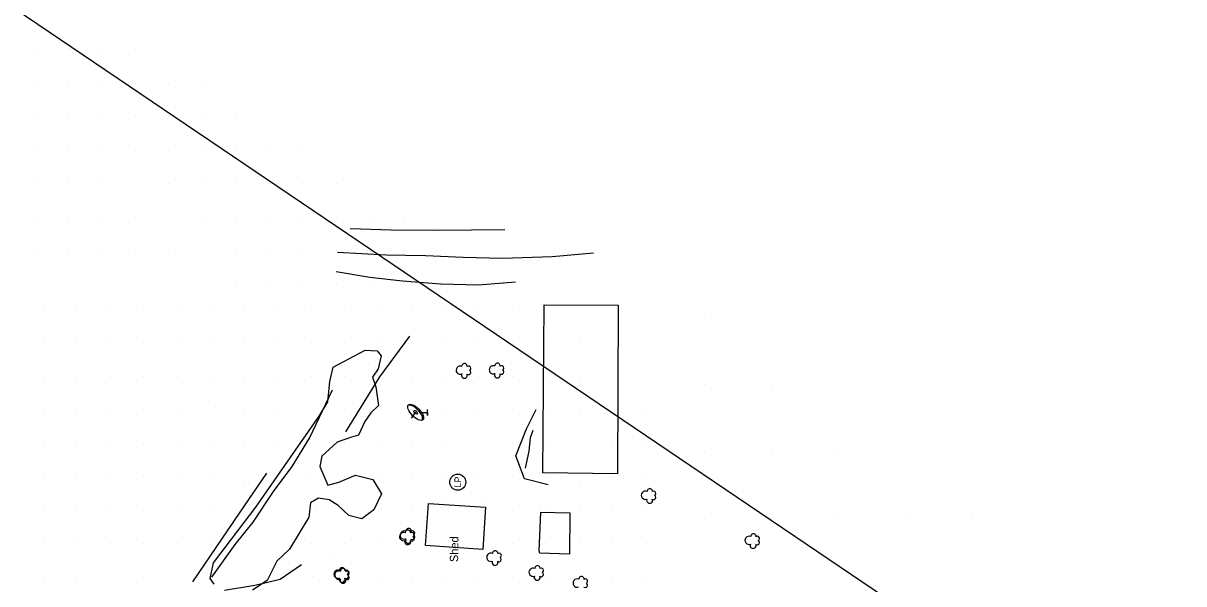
# Model space of a CAD drawing. Extents: x 19528164 to 19545171, y 7585743 to 7602745.
# Drawn here: x 19534893 to 19535586, y 7588311 to 7588646 of the extents above; entities that cross this region are included whole.
import ezdxf

# ---------------------------------------------------------------- set-up
doc = ezdxf.new("R2010")
doc.units = 0
for name, color, linetype in [('PhoBreakLine', 7, 'Continuous'), ('PhoBuilding', 7, 'Continuous'), ('PhoFence', 7, 'Continuous'), ('PhoISAEPoints', 7, 'Continuous'), ('PhoNotesDesign', 7, 'Continuous'), ('PhoSurveyLimits', 7, 'Continuous'), ('PhoVegetation', 7, 'Continuous'), ('SurBreakLine', 7, 'Continuous'), ('SurEdgeEntranceUnpaved', 7, 'Continuous'), ('SurNaturalCells', 7, 'Continuous')]:
    doc.layers.add(name, color=color, linetype=linetype)

# ---------------------------------------------------------------- blocks, each defined once
blk = doc.blocks.new('TRDC')
at = {"layer": 'PhoVegetation'}
for centre, radius, start, end in [((-6, -1.1), 3.52, 65.4824, 294.5175), ((0.1, 4), 4.92, 338.2051, 201.7949), ((4.9, -1.1), 3.21, 265.9982, 94.0018), ((-2.4, -5.9), 2.68, 142.7501, 335.3223), ((2.5, -5.8), 2.67, 206.5242, 35.4033)]:
    blk.add_arc(centre, radius, start, end, dxfattribs=at)

msp = doc.modelspace()

# ---------------------------------------------------------------- linework, layer by layer
at = {"layer": 'PhoBreakLine'}
for points in [[(19535180.52, 7588522.42), (19535140.77, 7588522.02), (19535112.64, 7588522.08), (19535088.25, 7588522.91)], [(19535080.57, 7588509.01), (19535109.62, 7588507.49), (19535133.15, 7588507.03), (19535155.59, 7588505.99), (19535179.13, 7588505.48), (19535208.86, 7588506.51), (19535233.44, 7588508.66)], [(19535186.86, 7588491.18), (19535164.83, 7588489.36), (19535142.23, 7588489.8), (19535119.54, 7588491.76), (19535100, 7588493.78), (19535079.79, 7588497.34)], [(19535085.63, 7588401.6), (19535105.96, 7588434.54), (19535123.82, 7588458.81)], [(19535005.58, 7588314.88), (19535019.47, 7588334.48), (19535030.39, 7588347.72), (19535042.37, 7588366.07), (19535053.67, 7588381.07), (19535064.02, 7588397.86), (19535077.73, 7588426.83)], [(19535206.33, 7588370.01), (19535192.35, 7588373.72), (19535187.07, 7588387.28), (19535193.48, 7588403.4), (19535199.3, 7588415.1)], [(19535192.97, 7588379.93), (19535195.03, 7588390.25), (19535195.89, 7588398.28), (19535197.49, 7588402.63)], [(19535013.09, 7588307.18), (19535031.38, 7588310.13), (19535046.51, 7588313.77), (19535059.16, 7588322.43)]]:
    msp.add_lwpolyline(points, dxfattribs=at)
at = {"layer": 'PhoBuilding'}
for points in [[(19535203.26, 7588377.18), (19535204.04, 7588477.59), (19535248.3, 7588477.29), (19535247.76, 7588376.67), (19535203.26, 7588377.18)], [(19535134.93, 7588358.89), (19535169.1, 7588356.65), (19535167.45, 7588331.51), (19535133.28, 7588333.75)], [(19535201.04, 7588330.65), (19535202.05, 7588353.65), (19535219.41, 7588353.32), (19535219.08, 7588328.67), (19535201.44, 7588329.33)]]:
    msp.add_lwpolyline(points, close=True, dxfattribs=at)
at = {"layer": 'PhoFence'}
msp.add_lwpolyline([(19534994.27, 7588312.05), (19535022.58, 7588353.76), (19535038.46, 7588376.96)], dxfattribs=at)
at = {"layer": 'PhoISAEPoints'}
for p, q in [((19534900, 7588590), (19534900, 7588590)), ((19534900, 7588570), (19534900, 7588570)), ((19534920, 7588570), (19534920, 7588570)), ((19534900, 7588550), (19534900, 7588550)), ((19534920, 7588550), (19534920, 7588550)), ((19534940, 7588550), (19534940, 7588550)), ((19534900, 7588530), (19534900, 7588530)), ((19534920, 7588530), (19534920, 7588530)), ((19534940, 7588530), (19534940, 7588530)), ((19534960, 7588530), (19534960, 7588530)), ((19534900, 7588510), (19534900, 7588510)), ((19534920, 7588510), (19534920, 7588510)), ((19534940, 7588510), (19534940, 7588510)), ((19534960, 7588510), (19534960, 7588510)), ((19534980, 7588510), (19534980, 7588510)), ((19535020, 7588490), (19535020, 7588490)), ((19534905, 7588475), (19534905, 7588475)), ((19534925, 7588475), (19534925, 7588475)), ((19534945, 7588475), (19534945, 7588475)), ((19534965, 7588475), (19534965, 7588475)), ((19534985, 7588475), (19534985, 7588475)), ((19535005, 7588475), (19535005, 7588475)), ((19535025, 7588475), (19535025, 7588475)), ((19534905, 7588455), (19534905, 7588455)), ((19534925, 7588455), (19534925, 7588455)), ((19534945, 7588455), (19534945, 7588455)), ((19534965, 7588455), (19534965, 7588455)), ((19534985, 7588455), (19534985, 7588455)), ((19535005, 7588455), (19535005, 7588455)), ((19535025, 7588455), (19535025, 7588455)), ((19535045, 7588455), (19535045, 7588455)), ((19535065, 7588455), (19535065, 7588455)), ((19534905, 7588435), (19534905, 7588435)), ((19534925, 7588435), (19534925, 7588435)), ((19534945, 7588435), (19534945, 7588435)), ((19534965, 7588435), (19534965, 7588435)), ((19534985, 7588435), (19534985, 7588435)), ((19535005, 7588435), (19535005, 7588435)), ((19535025, 7588435), (19535025, 7588435)), ((19535045, 7588435), (19535045, 7588435)), ((19535065, 7588435), (19535065, 7588435)), ((19535085, 7588435), (19535085, 7588435)), ((19534905, 7588415), (19534905, 7588415)), ((19534925, 7588415), (19534925, 7588415)), ((19534945, 7588415), (19534945, 7588415)), ((19534965, 7588415), (19534965, 7588415)), ((19534985, 7588415), (19534985, 7588415)), ((19535007.65, 7588416.93), (19535007.65, 7588416.93)), ((19535025, 7588415), (19535025, 7588415)), ((19535045, 7588415), (19535045, 7588415)), ((19535085, 7588415), (19535085, 7588415)), ((19535105, 7588415), (19535105, 7588415)), ((19534905, 7588395), (19534905, 7588395)), ((19534925, 7588395), (19534925, 7588395)), ((19534945, 7588395), (19534945, 7588395)), ((19534965, 7588395), (19534965, 7588395)), ((19534985, 7588395), (19534985, 7588395)), ((19535005, 7588395), (19535005, 7588395)), ((19535025, 7588395), (19535025, 7588395)), ((19535045, 7588395), (19535045, 7588395)), ((19535085, 7588395), (19535085, 7588395)), ((19535105, 7588395), (19535105, 7588395)), ((19535125, 7588395), (19535125, 7588395)), ((19535145, 7588395), (19535145, 7588395)), ((19535063.88, 7588376.86), (19535063.88, 7588376.86)), ((19534905, 7588375), (19534905, 7588375)), ((19534925, 7588375), (19534925, 7588375)), ((19534945, 7588375), (19534945, 7588375)), ((19534965, 7588375), (19534965, 7588375)), ((19534985, 7588375), (19534985, 7588375)), ((19535005, 7588375), (19535005, 7588375)), ((19535085, 7588375), (19535085, 7588375)), ((19535105, 7588375), (19535105, 7588375)), ((19535125, 7588375), (19535125, 7588375)), ((19535145, 7588375), (19535145, 7588375)), ((19535165, 7588375), (19535165, 7588375)), ((19535025.11, 7588368.9), (19535025.11, 7588368.9)), ((19535145.96, 7588361.36), (19535145.96, 7588361.36)), ((19535167.49, 7588359.83), (19535167.49, 7588359.83)), ((19534905, 7588355), (19534905, 7588355)), ((19534925, 7588355), (19534925, 7588355)), ((19534945, 7588355), (19534945, 7588355)), ((19534965, 7588355), (19534965, 7588355)), ((19534985, 7588355), (19534985, 7588355)), ((19535005, 7588355), (19535005, 7588355)), ((19535067.36, 7588354.34), (19535067.36, 7588354.34)), ((19535085, 7588355), (19535085, 7588355)), ((19535105, 7588355), (19535105, 7588355)), ((19535125, 7588355), (19535125, 7588355)), ((19534905, 7588335), (19534905, 7588335)), ((19534925.42, 7588335.97), (19534925.42, 7588335.97)), ((19534945, 7588335), (19534945, 7588335)), ((19534965, 7588335), (19534965, 7588335)), ((19534985, 7588335), (19534985, 7588335)), ((19535005, 7588335), (19535005, 7588335)), ((19535056.79, 7588337.85), (19535056.79, 7588337.85)), ((19535065, 7588335), (19535065, 7588335)), ((19535085, 7588335), (19535085, 7588335)), ((19535105, 7588335), (19535105, 7588335)), ((19535125, 7588335), (19535125, 7588335)), ((19535147.45, 7588332.11), (19535147.45, 7588332.11)), ((19535168.44, 7588331.03), (19535168.44, 7588331.03)), ((19535045.88, 7588325.22), (19535045.88, 7588325.22)), ((19535078.4, 7588327.09), (19535078.4, 7588327.09)), ((19534905, 7588315), (19534905, 7588315)), ((19534925, 7588315), (19534925, 7588315)), ((19534965, 7588315), (19534965, 7588315)), ((19535065.97, 7588315.29), (19535065.97, 7588315.29)), ((19535065.97, 7588315.29), (19535065.97, 7588315.29)), ((19535085, 7588315), (19535085, 7588315)), ((19535105, 7588315), (19535105, 7588315)), ((19535125, 7588315), (19535125, 7588315)), ((19535145, 7588315), (19535145, 7588315)), ((19535165, 7588315), (19535165, 7588315))]:
    msp.add_line(p, q, dxfattribs=at)
at = {"layer": 'PhoSurveyLimits'}
msp.add_lwpolyline([(19533878.26, 7590287.69), (19534414.23, 7589271.02), (19534620.47, 7588835.55), (19535976.6, 7587917.86), (19535872.2, 7587743.02), (19536196.76, 7587523.02), (19536087.66, 7587353.22), (19535761.89, 7587557.7), (19535245.62, 7586693.59), (19535240.5, 7586278.66), (19534925.52, 7586278.66), (19534905.11, 7587015.02), (19534733.57, 7587498.57), (19533471.56, 7588328.44)], dxfattribs=at)
at = {"layer": 'PhoVegetation'}
msp.add_lwpolyline([(19535007.1, 7588310.73), (19535004.64, 7588314.07), (19535006.7, 7588323.37), (19535031.87, 7588356.72), (19535069.76, 7588411.12), (19535074.94, 7588419.69), (19535076.06, 7588431.82), (19535078.05, 7588440.24), (19535097.22, 7588450.57), (19535104.4, 7588450.14), (19535106.65, 7588447.11), (19535104.86, 7588439.31), (19535101.52, 7588434.39), (19535103.48, 7588428.66), (19535105.06, 7588417.44), (19535100.55, 7588413.1), (19535097.01, 7588407.89), (19535093.28, 7588399.64), (19535089.05, 7588398.57), (19535080.46, 7588395.54), (19535071.39, 7588387.19), (19535070.12, 7588381.04), (19535074.81, 7588369.92), (19535081.47, 7588371.59), (19535091.48, 7588375.85), (19535101.71, 7588373.29), (19535106.83, 7588364.66), (19535102.35, 7588355.11), (19535095.22, 7588349.7), (19535087.47, 7588351.7), (19535080.96, 7588357.67), (19535075.74, 7588360.99), (19535069.35, 7588362.08), (19535064.57, 7588359.28), (19535063.57, 7588350.69), (19535051.91, 7588331.57), (19535044.5, 7588324.46), (19535038.75, 7588312.82), (19535029.94, 7588307.12)], dxfattribs=at)
msp.add_lwpolyline([(19535007.1, 7588310.73), (19535004.64, 7588314.07), (19535006.7, 7588323.37), (19535031.87, 7588356.72), (19535069.76, 7588411.12), (19535074.94, 7588419.69), (19535076.06, 7588431.82), (19535078.05, 7588440.24), (19535097.22, 7588450.57), (19535104.4, 7588450.14), (19535106.65, 7588447.11), (19535104.86, 7588439.31), (19535101.52, 7588434.39), (19535103.48, 7588428.66), (19535105.06, 7588417.44), (19535100.55, 7588413.1), (19535097.01, 7588407.89), (19535093.28, 7588399.64), (19535089.05, 7588398.57), (19535080.46, 7588395.54), (19535071.39, 7588387.19), (19535070.12, 7588381.04), (19535074.81, 7588369.92), (19535081.47, 7588371.59), (19535091.48, 7588375.85), (19535101.71, 7588373.29), (19535106.83, 7588364.66), (19535102.35, 7588355.11), (19535095.22, 7588349.7), (19535087.47, 7588351.7), (19535080.96, 7588357.67), (19535075.74, 7588360.99), (19535069.35, 7588362.08), (19535064.57, 7588359.28), (19535063.57, 7588350.69), (19535051.91, 7588331.57), (19535044.5, 7588324.46), (19535038.75, 7588312.82), (19535029.94, 7588307.12)], dxfattribs=at)
for centre, radius, start, end in [((19535153.93, 7588438.55), 2.46, 67.09808, 290.68793), ((19535156.49, 7588440.9), 1.6, 354.8912, 182.89482), ((19535158.84, 7588439.65), 1.34, 295.41717, 124.29635), ((19535173.65, 7588438.75), 2.46, 67.09808, 290.68793), ((19535176.2, 7588441.1), 1.6, 354.8912, 182.89482), ((19535178.55, 7588439.85), 1.34, 295.41717, 124.29635), ((19535156.38, 7588435.48), 1.76, 154.37541, 23.41054), ((19535158.83, 7588437.23), 1.34, 231.64315, 64.21535), ((19535176.1, 7588435.69), 1.76, 154.37541, 23.41054), ((19535178.55, 7588437.44), 1.34, 231.64315, 64.21535), ((19535264.48, 7588363.82), 2.46, 67.09808, 290.68793), ((19535267.04, 7588366.17), 1.6, 354.8912, 182.89482), ((19535269.38, 7588362.51), 1.34, 231.64315, 64.21535), ((19535269.39, 7588364.92), 1.34, 295.41717, 124.29635), ((19535266.94, 7588360.76), 1.76, 154.37541, 23.41054), ((19535122.66, 7588341.49), 1.6, 354.8912, 182.89482), ((19535120.1, 7588339.15), 2.46, 67.09808, 290.68793), ((19535122.55, 7588336.08), 1.76, 154.37541, 23.41054), ((19535125, 7588337.83), 1.34, 231.64315, 64.21535), ((19535125.01, 7588340.25), 1.34, 295.41717, 124.29635), ((19535326.36, 7588336.87), 2.46, 67.09808, 290.68793), ((19535328.92, 7588339.21), 1.6, 354.8912, 182.89482), ((19535331.26, 7588335.55), 1.34, 231.64315, 64.21535), ((19535331.27, 7588337.97), 1.34, 295.41717, 124.29635), ((19535172.21, 7588326.77), 2.46, 67.09808, 290.68793), ((19535174.77, 7588329.11), 1.6, 354.8912, 182.89482), ((19535177.12, 7588327.87), 1.34, 295.41717, 124.29635), ((19535328.81, 7588333.8), 1.76, 154.37541, 23.41054), ((19535174.66, 7588323.7), 1.76, 154.37541, 23.41054), ((19535177.11, 7588325.45), 1.34, 231.64315, 64.21535), ((19535199.97, 7588320.18), 1.6, 354.8912, 182.89482), ((19535080.93, 7588316.68), 2.46, 67.09808, 290.68793), ((19535083.38, 7588313.61), 1.76, 154.37541, 23.41054), ((19535083.48, 7588319.02), 1.6, 354.8912, 182.89482), ((19535085.82, 7588315.36), 1.34, 231.64315, 64.21535), ((19535085.83, 7588317.78), 1.34, 295.41717, 124.29635), ((19535197.42, 7588317.84), 2.46, 67.09808, 290.68793), ((19535199.87, 7588314.77), 1.76, 154.37541, 23.41054), ((19535202.32, 7588316.52), 1.34, 231.64315, 64.21535), ((19535202.33, 7588318.94), 1.34, 295.41717, 124.29635), ((19535226.29, 7588313.72), 1.6, 354.8912, 182.89482), ((19535223.73, 7588311.37), 2.46, 67.09808, 290.68793), ((19535228.63, 7588310.06), 1.34, 231.64315, 64.21535), ((19535228.64, 7588312.48), 1.34, 295.41717, 124.29635)]:
    msp.add_arc(centre, radius, start, end, dxfattribs=at)
at = {"layer": 'SurBreakLine'}
msp.add_lwpolyline([(19535085.63, 7588401.6), (19535105.96, 7588434.54), (19535123.82, 7588458.81)], dxfattribs=at)
at = {"layer": 'SurEdgeEntranceUnpaved'}
for p, q in [((19534900, 7588630), (19534900, 7588630)), ((19534920, 7588630), (19534920, 7588630)), ((19534940, 7588630), (19534940, 7588630)), ((19534960, 7588630), (19534960, 7588630)), ((19534900, 7588610), (19534900, 7588610)), ((19534920, 7588610), (19534920, 7588610)), ((19534940, 7588610), (19534940, 7588610)), ((19534960, 7588610), (19534960, 7588610)), ((19534980, 7588610), (19534980, 7588610)), ((19535000, 7588610), (19535000, 7588610)), ((19534920, 7588590), (19534920, 7588590)), ((19534940, 7588590), (19534940, 7588590)), ((19534960, 7588590), (19534960, 7588590)), ((19534980, 7588590), (19534980, 7588590)), ((19535000, 7588590), (19535000, 7588590)), ((19535020, 7588590), (19535020, 7588590)), ((19534940, 7588570), (19534940, 7588570)), ((19534960, 7588570), (19534960, 7588570)), ((19534980, 7588570), (19534980, 7588570)), ((19535000, 7588570), (19535000, 7588570)), ((19535020, 7588570), (19535020, 7588570)), ((19535040, 7588570), (19535040, 7588570)), ((19535060, 7588570), (19535060, 7588570)), ((19534980, 7588550), (19534980, 7588550)), ((19535000, 7588550), (19535000, 7588550)), ((19535020, 7588550), (19535020, 7588550)), ((19535040, 7588550), (19535040, 7588550)), ((19535060, 7588550), (19535060, 7588550)), ((19535080, 7588550), (19535080, 7588550)), ((19535000, 7588530), (19535000, 7588530)), ((19535020, 7588530), (19535020, 7588530)), ((19535040, 7588530), (19535040, 7588530)), ((19535060, 7588530), (19535060, 7588530)), ((19535080, 7588530), (19535080, 7588530)), ((19535100, 7588530), (19535100, 7588530)), ((19535120, 7588530), (19535120, 7588530)), ((19535020, 7588510), (19535020, 7588510)), ((19535040, 7588510), (19535040, 7588510)), ((19535060, 7588510), (19535060, 7588510)), ((19535080, 7588510), (19535080, 7588510)), ((19535100, 7588510), (19535100, 7588510)), ((19535120, 7588510), (19535120, 7588510)), ((19535140, 7588510), (19535140, 7588510)), ((19535040, 7588490), (19535040, 7588490)), ((19535060, 7588490), (19535060, 7588490)), ((19535080, 7588490), (19535080, 7588490)), ((19535100, 7588490), (19535100, 7588490)), ((19535120, 7588490), (19535120, 7588490)), ((19535140, 7588490), (19535140, 7588490)), ((19535160, 7588490), (19535160, 7588490)), ((19535180, 7588490), (19535180, 7588490)), ((19535045, 7588475), (19535045, 7588475)), ((19535065, 7588475), (19535065, 7588475)), ((19535085, 7588475), (19535085, 7588475)), ((19535105, 7588475), (19535105, 7588475)), ((19535125, 7588475), (19535125, 7588475)), ((19535145, 7588475), (19535145, 7588475)), ((19535165, 7588475), (19535165, 7588475)), ((19535185, 7588475), (19535185, 7588475)), ((19535300, 7588470), (19535300, 7588470)), ((19535085, 7588455), (19535085, 7588455)), ((19535105, 7588455), (19535105, 7588455)), ((19535125, 7588455), (19535125, 7588455)), ((19535145, 7588455), (19535145, 7588455)), ((19535165, 7588455), (19535165, 7588455)), ((19535185, 7588455), (19535185, 7588455)), ((19535205, 7588455), (19535205, 7588455)), ((19535225, 7588455), (19535225, 7588455)), ((19535099.1, 7588442.79), (19535099.1, 7588442.79)), ((19535199.81, 7588440.86), (19535199.81, 7588440.86)), ((19535085, 7588435), (19535085, 7588435)), ((19535125, 7588435), (19535125, 7588435)), ((19535145, 7588435), (19535145, 7588435)), ((19535165, 7588435), (19535165, 7588435)), ((19535185, 7588435), (19535185, 7588435)), ((19535205, 7588435), (19535205, 7588435)), ((19535225, 7588435), (19535225, 7588435)), ((19535300, 7588430), (19535300, 7588430)), ((19535340, 7588430), (19535340, 7588430)), ((19535201.52, 7588418.97), (19535201.52, 7588418.97)), ((19535105, 7588415), (19535105, 7588415)), ((19535125, 7588415), (19535125, 7588415)), ((19535145, 7588415), (19535145, 7588415)), ((19535165, 7588415), (19535165, 7588415)), ((19535185, 7588415), (19535185, 7588415)), ((19535205, 7588415), (19535205, 7588415)), ((19535225, 7588415), (19535225, 7588415)), ((19535265, 7588415), (19535265, 7588415)), ((19535125, 7588395), (19535125, 7588395)), ((19535145, 7588395), (19535145, 7588395)), ((19535185, 7588395), (19535185, 7588395)), ((19535205, 7588395), (19535205, 7588395)), ((19535245, 7588395), (19535245, 7588395)), ((19535265, 7588395), (19535265, 7588395)), ((19535300, 7588390), (19535300, 7588390)), ((19535300, 7588390), (19535300, 7588390)), ((19535300, 7588390), (19535300, 7588390)), ((19535340, 7588390), (19535340, 7588390)), ((19535380, 7588390), (19535380, 7588390)), ((19535185, 7588375), (19535185, 7588375)), ((19535205, 7588375), (19535205, 7588375)), ((19535245, 7588375), (19535245, 7588375)), ((19535265, 7588375), (19535265, 7588375)), ((19535225.78, 7588369.42), (19535225.78, 7588369.42)), ((19535185, 7588355), (19535185, 7588355)), ((19535205, 7588355), (19535205, 7588355)), ((19535225, 7588355), (19535225, 7588355)), ((19535245, 7588355), (19535245, 7588355)), ((19535265, 7588355), (19535265, 7588355)), ((19535300, 7588350), (19535300, 7588350)), ((19535300, 7588350), (19535300, 7588350)), ((19535300, 7588350), (19535300, 7588350)), ((19535340, 7588350), (19535340, 7588350)), ((19535340, 7588350), (19535340, 7588350)), ((19535340, 7588350), (19535340, 7588350)), ((19535380, 7588350), (19535380, 7588350)), ((19535380, 7588350), (19535380, 7588350)), ((19535380, 7588350), (19535380, 7588350)), ((19535420, 7588350), (19535420, 7588350)), ((19535460, 7588350), (19535460, 7588350)), ((19535185, 7588335), (19535185, 7588335)), ((19535205, 7588335), (19535205, 7588335)), ((19535225, 7588335), (19535225, 7588335)), ((19535245, 7588335), (19535245, 7588335)), ((19535265, 7588335), (19535265, 7588335)), ((19535185, 7588315), (19535185, 7588315)), ((19535205, 7588315), (19535205, 7588315)), ((19535225, 7588315), (19535225, 7588315)), ((19535245, 7588315), (19535245, 7588315)), ((19535265, 7588315), (19535265, 7588315))]:
    msp.add_line(p, q, dxfattribs=at)
at = {"layer": 'SurNaturalCells'}
msp.add_line((19535127.3, 7588413.37), (19535124.58, 7588409.88), dxfattribs=at)
msp.add_line((19535127.3, 7588413.37), (19535124.58, 7588409.88), dxfattribs=at)
msp.add_lwpolyline([(19535130.85, 7588413.3), (19535134.39, 7588413.23), (19535134.35, 7588411.46), (19535134.42, 7588415)], dxfattribs=at)
msp.add_lwpolyline([(19535130.85, 7588413.3), (19535134.39, 7588413.23), (19535134.35, 7588411.46), (19535134.42, 7588415)], dxfattribs=at)
msp.add_circle((19535152.45, 7588371.66), 4.8, dxfattribs=at)
for major_axis, ratio in [((4.3, -4.47), 0.428571), ((4.3, -4.47), 0.428571), ((0.921, -0.957), 0.5), ((0.921, -0.957), 0.5)]:
    msp.add_ellipse((19535127.3, 7588413.37), major_axis=major_axis, ratio=ratio, dxfattribs=at)
msp.add_ellipse((19535126.79, 7588412.87), major_axis=(4.3, -4.47), ratio=0.428571, start_param=0.159141, end_param=2.993624, dxfattribs=at)
msp.add_ellipse((19535126.79, 7588412.87), major_axis=(4.3, -4.47), ratio=0.428571, start_param=0.159141, end_param=2.993624, dxfattribs=at)

# ---------------------------------------------------------------- block references
at = {"layer": 'PhoVegetation', "xscale": 0.49999999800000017, "yscale": 0.49999999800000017, "rotation": 88.89301078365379}
for p in [(19535122.5, 7588339.97), (19535083.43, 7588316.04)]:
    msp.add_blockref('TRDC', p, dxfattribs=at)

# ---------------------------------------------------------------- texts
at = {"layer": 'PhoNotesDesign'}
msp.add_text('Shed', height=4.92, rotation=88.89301, dxfattribs=at).set_placement((19535152.6, 7588323.85))
at = {"layer": 'SurNaturalCells'}
msp.add_text('LP', height=3.999, rotation=88.89301, dxfattribs=at).set_placement((19535154.39, 7588368.44))

doc.saveas('drawing.dxf')
